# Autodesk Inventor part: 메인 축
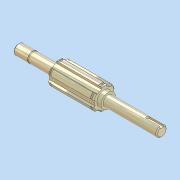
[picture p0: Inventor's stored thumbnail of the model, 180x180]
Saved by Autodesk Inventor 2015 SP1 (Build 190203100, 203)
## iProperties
Created: 2012-05
Part Number: 메인 축
Document SubType Name: 모델링
Designer: SeoGD™
Mass: 168.352 g
Surface Area: 72.5104 cm^2
Volume: 21.4461 cm^3
Density: 7.85 g/cm^3
Material: 강철, 연강
Appearance: 반연마
변환 표준: STEP AP214IS
파일 이름: C:\Users\SeoGD\Desktop\?쒗뿕\硫붿씤 異?.stp
전처리기: Build: 253, Release: 2010 SP1 - Date: Wed 07/29/2009
전송 단위: 밀리미터
불확실성: 0.01
Author: SeoGD™
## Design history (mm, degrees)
sketch "스케치1"
  geometry: L1 (-69.5, 0)-(69.5, 0); L2 (69.5, 0)-(69.5, 5); L3 (69.5, 5)-(55.5, 5); L4 (55.5, 5)-(55.5, 4.8); L5 (55.5, 4.8)-(54.35, 4.8); L6 (54.35, 4.8)-(54.35, 5); L7 (54.35, 5)-(30.5, 5); L8 (30.5, 5)-(30.5, 9); L9 (30.5, 9)-(-13.5, 9); L10 (-13.5, 9)-(-13.5, 7); L11 (-13.5, 7)-(-17.5, 7); L12 (-17.5, 7)-(-17.5, 5); L13 (-17.5, 5)-(-69.5, 5); L14 (-69.5, 5)-(-69.5, 0); 2 further points
  constraints: 28 end point, 9 parallel, 4 collinear, 2 perpendicular, 1 coincident, 1 horizontal, 1 midpoint
  dimensions: "d2" = 1.15 distance between parallel lines of L6 L4; "d3" = 10 diameter of L3 L1; "d4" = 9.6 diameter of L5 L1; "d6" = 44 distance between parallel lines of L10 L8; "d7" = 4 distance between parallel lines of L12 L10; "d8" = 14 diameter of L11 L1; "d9" = 18 diameter of L9 L1; "d33" = 52 distance from line of L12.end L14; "d37" = 39 distance between parallel lines of L8 L2; "d38" = 14 distance between parallel lines of L2 L4
revolve "회전1" sketch "스케치1" stored, may be unused: angle "d10" = 90 deg
sketch "스케치2"
  geometry: L1 (2.5, 10.712)-(2.5, 8.646); L2 (-2.5, 10.712)-(-2.5, 8.646); A1 r 9 centre (0, 0) between (2.5, 8.646) and (-2.5, 8.646) reference; A2 r 11 centre (0, 0) between (2.5, 10.712) and (-2.5, 10.712); 1 further point
  constraints: 4 end point, 4 point on circle, 2 parallel, 1 centre point, 1 coincident, 1 vertical
  dimensions: "d11" = 22 diameter of A2; "d12" = 5 distance between parallel lines of L1 L2
extrude "돌출1" join sketch "스케치2" stored distance "d13" = 10; taper "d14" = 0 deg
chamfer "모따기1" distance "d15" = 1; stored, may be unused: second distance "d16" = 2, angle "d17" = 45 deg
node "작업 평면1"
node "작업 평면2"
sketch "스케치3"
  geometry: L1 (2.5, 10.712)-(2.5, 10.198); L2 (-2.5, 10.712)-(-2.5, 10.198); A1 r 11 centre (0, 0) between (2.5, 10.712) and (-2.5, 10.712) reference; A2 r 10.5 centre (0, 0) between (2.5, 10.198) and (-2.5, 10.198); 1 further point
  constraints: 4 end point, 2 point on circle, 1 centre point, 1 coincident, 1 parallel, 1 vertical
  dimensions: "d19" = 21 diameter of A2
extrude "돌출2" cut sketch "스케치3" distance "d20" = 1.35; taper "d21" = 0 deg
node "작업 평면3"
sketch "스케치4"
  geometry: L1 (-26, -5)-(-26, 5) reference; L2 (-26, 1.5)-(-12.5, 1.5); L3 (-12.5, -1.5)-(-26, -1.5); A1 r 1.5 centre (-12.5, 0) between (-12.5, -1.5) and (-12.5, 1.5); 2 further points
  constraints: 4 end point, 2 perpendicular, 2 point on circle, 2 point on line, 2 tangent, 1 centre point, 1 horizontal alignment, 1 midpoint
  dimensions: "d25" = 3 distance between parallel lines of L3 L2; "d26" = 15 dimension on A1 L1
extrude "돌출3" cut sketch "스케치4" distance "d27" = 1.8; taper "d28" = 0 deg
chamfer "모따기2" distance "d29" = 1; stored, may be unused: second distance "d30" = 2, angle "d31" = 45 deg
node "솔리드1"
node "솔리드 본체"
node "곡면 본체"
mirror "대칭1"
pattern_circular "원형 패턴1" dims "d23" = 360 deg
node "솔리드2"
other parameters: "d18" = -1.65
